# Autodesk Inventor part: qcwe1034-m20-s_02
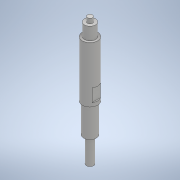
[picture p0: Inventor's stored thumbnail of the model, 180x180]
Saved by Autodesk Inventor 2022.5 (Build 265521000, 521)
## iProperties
Created: 2020-10
Part Number: qcwe1034-m20-s_02
Material: 一般
Document SubType Name: Modeling
Designer: ImaoCorp
Density: 1 g/cm^3
Appearance: 既定
Author: ImaoCorp
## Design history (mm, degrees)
feature "qcwe1034-m20-s_02"
node "ソリッド1"
